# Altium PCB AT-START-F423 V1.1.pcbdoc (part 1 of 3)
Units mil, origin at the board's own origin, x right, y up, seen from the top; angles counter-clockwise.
Board outline 13392.89 x 3532.45 mil, 2 copper layers (Top Layer, Bottom Layer); 137 components, 162 nets, 618 pads, 618 vias.
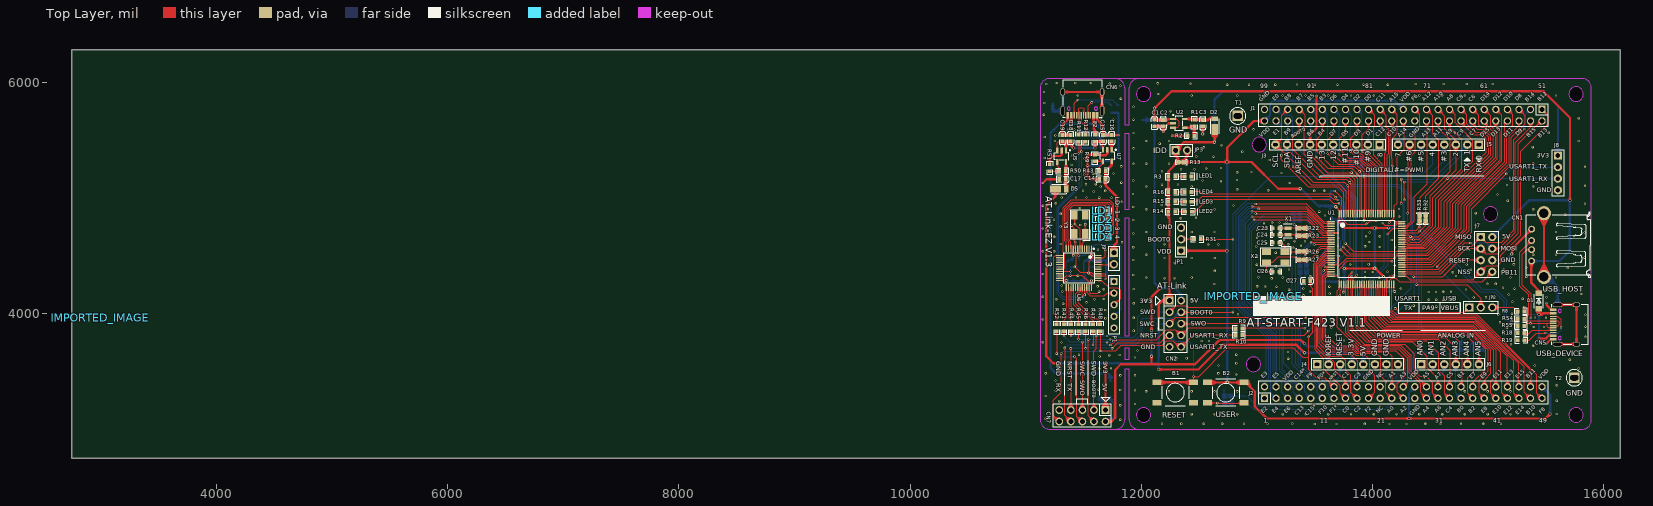
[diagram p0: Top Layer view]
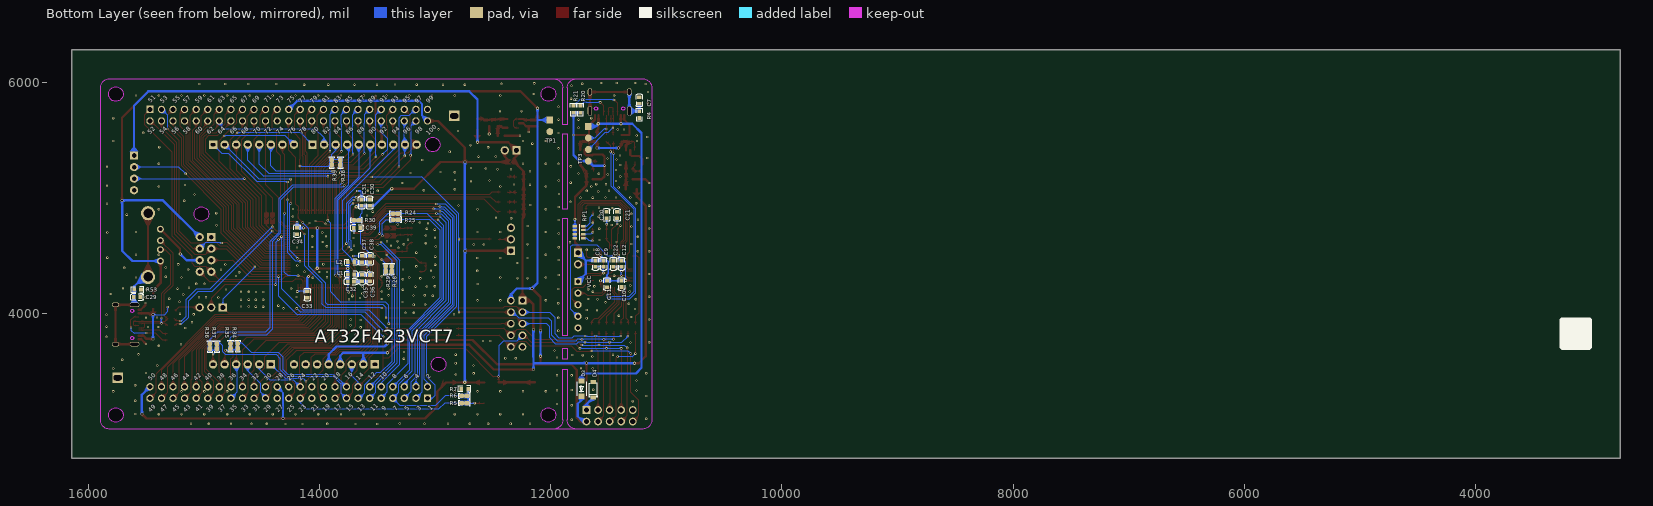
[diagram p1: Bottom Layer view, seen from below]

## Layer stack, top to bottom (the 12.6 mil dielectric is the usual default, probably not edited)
Top Layer: signal copper (thickness not stored)
Dielectric: dielectric 12.6, FR-4, Dk 4.8
Bottom Layer: signal copper (thickness not stored)

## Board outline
16142.89,2750 2750,2750 2750,6282.45 16142.89,6282.45
cut-out: 15823.04,5897.28 ccw(c15760.05,5896.97) 15697.06,5897.28 ccw(c15760.05,5897.59)
cut-out: 15823.04,3122.6 ccw(c15760.05,3122.29) 15697.06,3122.6 ccw(c15760.05,3122.91)
cut-out: 12082.89,3122.6 ccw(c12019.89,3122.6) 11956.9,3122.6 ccw(c12019.89,3122.6)
cut-out: 12082.89,5897.28 ccw(c12019.89,5897.28) 11956.9,5897.28 ccw(c12019.89,5897.28)
cut-out: 15082.49,4860.43 ccw(c15019.5,4860.02) 14956.51,4860.43 ccw(c15019.5,4860.84)
cut-out: 13032.49,3560.43 ccw(c12969.5,3560.02) 12906.51,3560.43 ccw(c12969.5,3560.84)
cut-out: 13082.49,5460.43 ccw(c13019.5,5460.02) 12956.51,5460.43 ccw(c13019.5,5460.84)

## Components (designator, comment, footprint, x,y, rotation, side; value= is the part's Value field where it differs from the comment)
B1 "BUTTON_SMT,6.0x6.0x4.5mm" BUTTON_SMT_6*6*5 12293.58,3316.11 r0 top
B2 "BUTTON_SMT,6.0x6.0x4.5mm_BUTTON_SMT_6*6*5" BUTTON_SMT_6*6*5 12730.58,3315.11 r0 top
C1 "CL10A106KP8NNNC" C0603 12113.62,5646.5 r90 top
C2 "CC0603KRX7R9BB104" C0603 12189.62,5645.5 r90 top
C3 "CL10A106KP8NNNC" C0603 12531.28,5645.68 r90 top
C7 "CC0603KRX7R9BB104" C0603 11234.18,5841.98 r270 bottom
C8 "CL10A475KO8NNNC" C0603 11613.28,4430.68 r90 bottom
C9 "CC0603KRX7R9BB104" C0603 11543.28,4430.68 r90 bottom
C10 "CC0603KRX7R9BB104" C0603 11388.28,4256.68 r90 bottom
C11 "CC0603KRX7R9BB104" C0603 11513.28,4255.68 r90 bottom
C12 "CC0603KRX7R9BB104" C0603 11388.28,4430.68 r90 bottom
C14 "CL10A106KP8NNNC" C0603 11663.28,5160.68 r0 top
C15 "CL10A106KP8NNNC" C0603 11668.28,5515.68 r270 top
C16 "CC0603KRX7R9BB104" C0603 11743.28,5515.68 r270 top
C17 "CL10A106KP8NNNC" C0603 11318.28,5160.68 r0 top
C18 "CL10A106KP8NNNC" C0603 11388.28,5515.68 r270 top
C19 "CC0603KRX7R9BB104" C0603 11318.28,5515.68 r270 top
C20 "CL10C220JB8NNNC" C0603 11516.28,4851.68 r270 bottom
C21 "CL10C220JB8NNNC" C0603 11425.28,4852.68 r270 bottom
C22 "CC0603KRX7R9BB104" C0603 11458.28,4430.68 r90 bottom
C23 "10pF" 0603_C-M 13163.28,4738.68 r180 top
C24 "10pF" 0603_C-M 13163.28,4679.68 r180 top
C25 "22pF_0603_C-M" 0603_C-M(1) 13163.88,4611.08 r180 top
C26 "22pF_0603_C-M" 0603_C-M(1) 13163.88,4361.08 r0 top
C27 "CC0603KRX7R9BB104" C0603 13431.58,4282.11 r0 top
C29 "CC0603KRX7R9BB104" C0603 15576.58,4141.11 r0 bottom
C30 "CL10A475KO8NNNC" C0603 13564.58,4958.11 r270 bottom
C31 "CC0603KRX7R9BB104" C0603 13634.58,4958.11 r270 bottom
C32 "CC0603KRX7R9BB104" C0603 13728.58,4275.11 r0 bottom
C33 "CC0603KRX7R9BB104" C0603 14104.58,4164.11 r90 bottom
C34 "CC0603KRX7R9BB104" C0603 14192.58,4713.11 r90 bottom
C35 "CL10A105KB8NNNC" C0603 13630.58,4306.11 r90 bottom
C36 "CC0603KRX7R9BB104" C0603 13561.58,4305.11 r90 bottom
C37 "CL10A105KB8NNNC" C0603 13631.58,4471.11 r270 bottom
C38 "CC0603KRX7R9BB104" C0603 13563.58,4471.11 r270 bottom
C39 "CC0603KRX7R9BB104" C0603 13674.58,4741.11 r0 bottom
CN1 "902-131A1011D10100" USB-A-TH__USB-AF-90 15427.89,4591.6 r90 top
CN2 "Z-21310110021001" HDR-TH_10P-P2.54-V-M-R2-C5-S2.54 12294.28,3911.68 r270 top
CN5 "TYPEC-304-BCP16" USB-C-SMD_TYPEC-304-BCP16#1 15662.58,3905.11 r90 top
CN6 "TYPEC-304-BCP16" USB-C-SMD_TYPEC-304-BCP16#2 11490.4,5815.68 r180 top
CN7 "Z-21310110021001" HDR-TH_10P-P2.54-V-M-R2-C5-S2.54 11490.38,3115.68 r180 top
D1 "1N5819HW-7-F" SOD-123_L2.8-W1.8-LS3.7-FD 15436.89,4106.6 r90 top
D2 "DFLS130L-7_POWERDI-123_L2.8-W1.8-LS3.7-RD" POWERDI-123_L2.8-W1.8-LS3.7-RD 12634.58,5637.11 r90 top
D3 "1N5819HW-7-F" SOD-123_L2.8-W1.8-LS3.7-FD 11733.89,3349.6 r270 bottom
D4 "SMF3.3A" SOD-123_L2.8-W1.8-LS3.7-RD 11631.88,3341.08 r90 bottom
D5 "DFLS130L-7_POWERDI-123_L2.8-W1.8-LS3.7-RD" POWERDI-123_L2.8-W1.8-LS3.7-RD 11303.28,5075.68 r0 top
F2 "SMD0603B050TF" R0603 11598.28,5515.68 r270 top
IMPORTED_IMAGE "IMPORTED_IMAGE" IMPORTED_IMAGE 3000,3964.11 r0 top
IMPORTED_IMAGE "IMPORTED_IMAGE" IMPORTED_IMAGE 12967.89,4147.6 r0 top
J1 "X6521WV-2x25H-C30D60" HDR-TH_50P-2.54-V-M-R2-C25-S2.54 14265.15,5715.15 r180 top
J2 "X6521WV-2x25H-C30D60" HDR-TH_50P-2.54-V-M-R2-C25-S2.54 14265.15,3316.57 r0 top
J3 "2.54-1*10P母" "AT-START-Connector 1x10" 13609.5,5460.43 r180 top
J4 "2.54-1*8P母环保" "AT-START-Connector 1x8" 13869.5,3560.43 r0 top
J5 "2.54-1*8P母环保" "AT-START-Connector 1x8" 14569.51,5460.43 r180 top
J6 "2.54-1*6P母" "AT-START-Connector 1x6" 14669.48,3560.43 r0 top
J7 "Header 4X2" HDR2X4 14934.51,4660.97 r270 top
J8 "Header 1x4" HDR1X4 15602.58,5366.11 r270 top
J9 "1X2P,Male,DIP_2.54" HDR1X2 11763.28,4525.68 r270 top
JP1 "Header 1x3" "HEADER 1X3" 12343.88,4542.08 r90 top
JP2 "Header 1x3" "HEADER 1X3" 14834.89,4052.61 r0 top
JP3 "NC(Header 1x2)" HDR1X2 12296.58,5411.11 r0 top
L1 "UPZ1608E601-1R0TF" L0603 13726.58,4339.11 r180 bottom
L2 "UPZ1608E601-1R0TF" L0603 13725.58,4444.11 r180 bottom
LD1 "RED" LED0603 11634.09,4889.92 r0 top
LD2 "GREEN" LED0603 11635.05,4815.83 r0 top
LD3 "BLUE" LED0603 11635.09,4738.92 r0 top
LD4 "YELLOW" LED0603 11635.05,4662.92 r0 top
LED1 "RED_LED0603(1)" LED0603 12373.58,5185.11 r0 top
LED2 "RED_LED0603" LED0603 12375.88,4879.08 r0 top
LED3 "YELLOW_LED0603" LED0603 12374.88,4965.08 r0 top
LED4 "GREEN_LED0603" LED0603 12373.88,5051.08 r0 top
P1 "HDR-M-2.54_1x5" HDR-M-2.54_1X5 11763.28,4075.68 r270 top
R1 "0603WAF5102T5E" R0603 12458.28,5647.68 r90 top
R2 "0603WAF1502T5E" R0603 12428.28,5536.68 r0 top
R3 "0603WAF1001T5E" R0603 12263.35,5184.27 r180 top
R4 "RC0603FR-071ML" R0603 11233.98,5719.99 r270 bottom
R5 "0Ω" SB-PAD 12745.89,3225.6 r180 bottom
R6 "NC_SB-PAD" SB-PAD 12745.89,3287.6 r180 bottom
R7 "0603WAF1003T5E" R0603 12743.58,3348.11 r180 bottom
R8 "0603WAF1002T5E" R0603 15282.23,4017.6 r0 top
R9 "0603WAF4700T5E" R0603 12844.55,3871.6 r0 top
R10 "0603WAF4700T5E" R0603 12844.55,3812.6 r0 top
R11 "0603WAF0000T5E" R0603 11458.28,5515.68 r270 top
R12 "0603WAF0000T5E" R0603 11518.28,5515.68 r270 top
R13 "0Ω" SB-PAD 12345.89,5308.6 r0 top
R14 "0603WAF1001T5E" R0603 12262.88,4880.08 r180 top
R15 "0603WAF1001T5E" R0603 12263.88,4967.08 r180 top
R16 "0603WAF1001T5E" R0603 12262.88,5050.08 r180 top
R18 "0603WAF5101T5E" R0603 15283.58,3831.11 r180 top
R19 "0603WAF5101T5E" R0603 15283.89,3768.6 r180 top
R20 "0603WAF5101T5E" R0603 11743.28,5765.68 r270 bottom
R21 "0603WAF5101T5E" R0603 11803.28,5765.68 r270 bottom
R22 "0Ω" SB-PAD 13386.17,4737.6 r180 top
R23 "0Ω" SB-PAD 13385.89,4672.6 r180 top
R24 "NC" SB-PAD 13340.58,4864.11 r180 bottom
R25 "NC" SB-PAD 13339.58,4810.11 r180 bottom
R26 "0Ω" SB-PAD 13384.89,4537.6 r180 top
R27 "0Ω" SB-PAD 13385.89,4464.6 r180 top
R28 "NC" SB-PAD 13373.58,4383.99 r270 bottom
R29 "NC" SB-PAD 13426.58,4386.11 r270 bottom
R30 "0Ω" SB-PAD 13678.11,4806.11 r180 bottom
R31 "0603WAF1002T5E" R0603 12484.88,4643.08 r0 top
R32 "NC_SB-PAD" SB-PAD 14458.58,4822.11 r270 top
R33 "NC_SB-PAD" SB-PAD 14405.58,4822.11 r270 top
R34 "0Ω" sb-pad 14706.89,3717.6 r270 bottom
R35 "NC_SB-PAD" sb-pad 14768.58,3718.11 r270 bottom
R36 "NC_SB-PAD" sb-pad 14946.58,3716.11 r270 bottom
R37 "0Ω" sb-pad 14885.89,3715.32 r270 bottom
R38 "NC_SB-PAD" SB-PAD 13817.88,5305.08 r270 bottom
R39 "0Ω" SB-PAD 13893.89,5305.6 r270 bottom
R41 "0603WAF330JT5E" R0603 11330.28,3876.68 r270 top
R43 "0603WAF4702T5E" R0603 11663.28,5230.68 r0 top
R44 "0603WAF330JT5E" R0603 11392.28,3876.68 r270 top
R45 "0603WAF330JT5E" R0603 11455.28,3876.68 r270 top
R46 "0603WAF330JT5E" R0603 11518.28,3876.68 r270 top
R47 "0603WAF330JT5E" R0603 11582.28,3876.68 r270 top
R48 "0603WAF330JT5E" R0603 11644.28,3876.68 r270 top
R49 "0603WAF1502T5E" R0603 11598.28,5345.68 r270 top
R50 "0603WAF5102T5E" R0603 11318.28,5230.68 r0 top
R51 "0603WAF1502T5E" R0603 11208.28,5260.68 r270 top
R52 "0603WAF330JT5E" R0603 11268.28,3876.68 r270 top
R53 "RC0603FR-071ML" R0603 15571.58,4207.11 r180 bottom
R54 "0603WAF220JT5E" R0603 15282.58,3954.11 r0 top
R55 "0603WAF220JT5E" R0603 15282.58,3892.11 r0 top
RP1 "1K" 0603*4,8P4R 11791.28,4756.68 r270 bottom
T1 "Testpoint_TESTHOOK" TESTHOOK 12833.58,5708.11 r0 top
T2 "Testpoint" TESTHOOK 15743.58,3444.11 r180 top
TP1 "2.54-1*2P母" "AT-START-TEST-POINT 1X2" 12007.58,5623.11 r270 bottom
TP3 "1X4P_2.54F" "HDR1X4 - TOP" 11674.63,5618.13 r90 bottom
U1 "AT32F423VCT7" LQFP-100_L14.0-W14.0-P0.50-LS16.0-TL 13946.58,4558.11 r0 top
U2 "RT9080N-08GJ5_SOT-23-5" SOT-23-5(1) 12339.62,5581.5 r0 top
U5 "RT9080N-08GJ5" SOT-23-5 11248.28,5345.68 r270 top
U6 "AT32F403ACxT7" LQFP-48_L7.0-W7.0-P0.50-LS9.0-BL 11460,4393.35 r180 top
U7 "RT9080N-08GJ5" SOT-23-5(1) 11643.28,5350.68 r270 top
X1 "32.768KHz" "XTAL_SOP - FC-12M" 13267.28,4738.68 r270 top
X2 "8MHz" OSC-SMD_4P-L5.0-W3.2-BL 13161.88,4488.08 r180 top
Y3 "8MHz" OSC-SMD_4P-L5.0-W3.2-BL 11468.28,4770.68 r90 top

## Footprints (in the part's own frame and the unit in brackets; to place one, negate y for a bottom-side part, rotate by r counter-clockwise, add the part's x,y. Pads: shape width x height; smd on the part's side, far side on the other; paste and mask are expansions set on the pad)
0603*4,8P4R [mm]
  rect 0.55x0.95 smd: 1(0,0) 4(2.7,0) 5(2.7,1.85) 8(0,1.85)
  rect 0.5x0.95 smd: 2(0.9,0) 3(1.8,0) 6(1.8,1.85) 7(0.9,1.85)
  silkscreen extent -0.43,0.94 3.1,0.94
0603_C-M [mil]
  rect 30x30 smd: 1(27.5,0) 2(-27.5,0)
  silkscreen extent -50,-21 50,21
0603_C-M(1) [mil]
  rect 30x30 smd: 1(27.5,0) 2(-27.5,0)
  silkscreen extent -50,-21 50,21
"AT-START-Connector 1x6" [mm]
  rect 1.86x1.86 hole 0.65 slot 1 at 0 deg: 1(-6.35,0)
  round 1.86 hole 0.65 slot 1 at 0 deg: 2(-3.81,0) 3(-1.27,0) 4(1.27,0) 5(3.81,0) 6(6.35,0)
  silkscreen extent -7.62,-1.17 7.62,1.27
"AT-START-Connector 1x8" [mm]
  rect 1.86x1.86 hole 0.65 slot 1 at 0 deg: 1(-8.89,0)
  round 1.86 hole 0.65 slot 1 at 0 deg: 2(-6.35,0) 3(-3.81,0) 4(-1.27,0) 5(1.27,0) 6(3.81,0) 7(6.35,0) 8(8.89,0)
  silkscreen extent -10.16,-1.17 10.16,1.27
"AT-START-Connector 1x10" [mm]
  rect 1.86x1.86 hole 0.65 slot 1 at 0 deg: 1(-11.43,0)
  round 1.86 hole 0.65 slot 1 at 0 deg: 2(-8.89,0) 3(-6.35,0) 4(-3.81,0) 5(-1.27,0) 6(1.27,0) 7(3.81,0) 8(6.35,0) 9(8.89,0) 10(11.43,0)
  silkscreen extent -12.7,-1.17 12.67,1.27
"AT-START-TEST-POINT 1X2" [mm]
  rect 1.5x1.5 smd: 1(-1.27,0)
  round 1.5 smd: 2(1.27,0)
BUTTON_SMT_6*6*5 [mm]
  rect 2x1.2 smd: 1(-4,2.25) 2(4,2.25) 3(-4,-2.25) 4(4,-2.25)
  silkscreen extent -3,-3 3,3
C0603 [mm]
  rect 0.8x0.9 smd: 1(-0.7,0) 2(0.7,0)
  silkscreen extent -1.41,-0.71 1.39,0.72
HDR1X2 [mm]
  rect 1.8x1.8 hole 1 slot 1.005 at 0 deg: 1(0,0)
  round 1.8 hole 1 slot 1.005 at 0 deg: 2(2.54,0)
  silkscreen extent -1.27,-1.27 3.81,1.27
HDR1X4 [mm]
  rect 1.8x1.8 hole 1: 1(0,0)
  round 1.8 hole 1: 2(2.54,0) 3(5.08,0) 4(7.62,0)
  silkscreen extent -1.27,-1.27 8.89,1.27
"HDR1X4 - TOP" [mm]
  rect 1.5x1.5 smd: 1(0,0)
  round 1.5 smd: 2(-2.54,0) 3(-5.08,0) 4(-7.62,0)
HDR2X4 [mm]
  rect 1.8x1.8 hole 1: 1(0,0)
  round 1.8 hole 1: 2(0,2.54) 3(2.54,0) 4(2.54,2.54) 5(5.08,0) 6(5.08,2.54) 7(7.62,0) 8(7.62,2.54)
  silkscreen extent -1.27,-1.27 8.89,3.81
HDR-M-2.54_1X5 [mil]
  rect 62x62 hole 35: 1(-200,0)
  round 62 hole 35: 2(-100,0) 3(0,0) 4(100,0) 5(200,0)
  silkscreen extent -250,-50 250,50
HDR-TH_10P-P2.54-V-M-R2-C5-S2.54 [mm]
  rect 1.7x1.7 hole 1.1: 1(-5.08,-1.27)
  round 1.7 hole 1.1: 2(-5.08,1.27) 3(-2.54,-1.27) 4(-2.54,1.27) 5(0,-1.27) 6(0,1.27) 7(2.54,-1.27) 8(2.54,1.27) 9(5.08,-1.27) 10(5.08,1.27)
  silkscreen extent -6.35,-2.54 6.35,2.54
HDR-TH_50P-2.54-V-M-R2-C25-S2.54 [mil]
  rect 63x63 hole 41.3: 1(-1200,-50)
  round 63 hole 41.3: 2(-1200,50) 3(-1100,-50) 4(-1100,50) 5(-1000,-50) 6(-1000,50) 7(-900,-50) 8(-900,50) 9(-800,-50) 10(-800,50) 11(-700,-50) 12(-700,50) 13(-600,-50) 14(-600,50) 15(-500,-50) 16(-500,50) 17(-400,-50) 18(-400,50) 19(-300,-50) 20(-300,50) 21(-200,-50) 22(-200,50) 23(-100,-50) 24(-100,50) 25(0,-50) 26(0,50) 27(100,-50) 28(100,50) 29(200,-50) 30(200,50) 31(300,-50) 32(300,50) 33(400,-50) 34(400,50) 35(500,-50) 36(500,50) 37(600,-50) 38(600,50) 39(700,-50) 40(700,50) 41(800,-50) 42(800,50) 43(900,-50) 44(900,50) 45(1000,-50) 46(1000,50) 47(1100,-50) 48(1100,50) 49(1200,-50) 50(1200,50)
  silkscreen extent -1250,-100 1250,100
"HEADER 1X3" [mm]
  rect 1.8x1.8 hole 1 slot 1.005 at 0 deg: 1(0,0)
  round 1.8 hole 1 slot 1.005 at 0 deg: 2(2.54,0) 3(5.08,0)
  silkscreen extent -1.27,-1.27 6.35,1.27
IMPORTED_IMAGE [mil]
L0603 [mil]
  rect 31.5x34 smd: 1(-27.6,0) 2(27.6,0)
  silkscreen extent -56,-26 56,26
LED0603 [mil]
  rect 36x32 smd: 1(-0.04,0.2) 2(60.96,0.2)
  silkscreen extent -28,-28 110,27
LQFP-48_L7.0-W7.0-P0.50-LS9.0-BL [mm]
  oval 0.27x1.5 smd: 1(-2.75,-4.25) 2(-2.25,-4.25) 3(-1.75,-4.25) 4(-1.25,-4.25) 5(-0.75,-4.25) 6(-0.25,-4.25) 7(0.25,-4.25) 8(0.75,-4.25) 9(1.25,-4.25) 10(1.75,-4.25) 11(2.25,-4.25) 12(2.75,-4.25) 25(2.75,4.25) 26(2.25,4.25) 27(1.75,4.25) 28(1.25,4.25) 29(0.75,4.25) 30(0.25,4.25) 31(-0.25,4.25) 32(-0.75,4.25) 33(-1.25,4.25) 34(-1.75,4.25) 35(-2.25,4.25) 36(-2.75,4.25)
  oval 1.5x0.27 smd: 13(4.25,-2.75) 14(4.25,-2.25) 15(4.25,-1.75) 16(4.25,-1.25) 17(4.25,-0.75) 18(4.25,-0.25) 19(4.25,0.25) 20(4.25,0.75) 21(4.25,1.25) 22(4.25,1.75) 23(4.25,2.25) 24(4.25,2.75) 37(-4.25,2.75) 38(-4.25,2.25) 39(-4.25,1.75) 40(-4.25,1.25) 41(-4.25,0.75) 42(-4.25,0.25) 43(-4.25,-0.25) 44(-4.25,-0.75) 45(-4.25,-1.25) 46(-4.25,-1.75) 47(-4.25,-2.25) 48(-4.25,-2.75)
  silkscreen extent -3.36,-4.34 3.3,3.34
LQFP-100_L14.0-W14.0-P0.50-LS16.0-TL [mil]
  oval 63x11.8 smd: 1(-305.1,236.2) 2(-305.1,216.5) 3(-305.1,196.9) 4(-305.1,177.2) 5(-305.1,157.5) 6(-305.1,137.8) 7(-305.1,118.1) 8(-305.1,98.4) 9(-305.1,78.7) 10(-305.1,59.1) 11(-305.1,39.4) 12(-305.1,19.7) 13(-305.1,0) 14(-305.1,-19.7) 15(-305.1,-39.4) 16(-305.1,-59.1) 17(-305.1,-78.7) 18(-305.1,-98.4) 19(-305.1,-118.1) 20(-305.1,-137.8) 21(-305.1,-157.5) 22(-305.1,-177.2) 23(-305.1,-196.8) 24(-305.1,-216.5) 25(-305.1,-236.2) 51(305.1,-236.2) 52(305.1,-216.5) 53(305.1,-196.8) 54(305.1,-177.2) 55(305.1,-157.5) 56(305.1,-137.8) 57(305.1,-118.1) 58(305.1,-98.4) 59(305.1,-78.7) 60(305.1,-59.1) 61(305.1,-39.4) 62(305.1,-19.7) 63(305.1,0) 64(305.1,19.7) 65(305.1,39.4) 66(305.1,59.1) 67(305.1,78.7) 68(305.1,98.4) 69(305.1,118.1) 70(305.1,137.8) 71(305.1,157.5) 72(305.1,177.2) 73(305.1,196.9) 74(305.1,216.5) 75(305.1,236.2)
  oval 11.8x63 smd: 26(-236.2,-305.1) 27(-216.5,-305.1) 28(-196.8,-305.1) 29(-177.2,-305.1) 30(-157.5,-305.1) 31(-137.8,-305.1) 32(-118.1,-305.1) 33(-98.4,-305.1) 34(-78.7,-305.1) 35(-59.1,-305.1) 36(-39.4,-305.1) 37(-19.7,-305.1) 38(0,-305.1) 39(19.7,-305.1) 40(39.4,-305.1) 41(59.1,-305.1) 42(78.7,-305.1) 43(98.4,-305.1) 44(118.1,-305.1) 45(137.8,-305.1) 46(157.5,-305.1) 47(177.2,-305.1) 48(196.9,-305.1) 49(216.5,-305.1) 50(236.2,-305.1) 76(236.2,305.1) 77(216.5,305.1) 78(196.9,305.1) 79(177.2,305.1) 80(157.5,305.1) 81(137.8,305.1) 82(118.1,305.1) 83(98.4,305.1) 84(78.7,305.1) 85(59.1,305.1) 86(39.4,305.1) 87(19.7,305.1) 88(0,305.1) 89(-19.7,305.1) 90(-39.4,305.1) 91(-59.1,305.1) 92(-78.7,305.1) 93(-98.4,305.1) 94(-118.1,305.1) 95(-137.8,305.1) 96(-157.5,305.1) 97(-177.2,305.1) 98(-196.8,305.1) 99(-216.5,305.1) 100(-236.2,305.1)
  silkscreen extent -315,-246 246,266
OSC-SMD_4P-L5.0-W3.2-BL [mm]
  rect 2x1.4 smd: 1(-2.05,-1.2) 2(2.05,-1.2) 3(2.05,1.2) 4(-2.05,1.2)
  silkscreen extent -3.46,-2.26 3.24,2.03
POWERDI-123_L2.8-W1.8-LS3.7-RD [mm]
  rect 2.4x1.5 smd: 1(-1.187,0)
  rect 1.05x1.5 smd: 2(1.187,0)
  silkscreen extent -2,-1 1.2,1
R0603 [mil]
  rect 31.75x34.02 smd: 1(-29.66,0) 2(29.66,0)
  silkscreen extent -55,-26 55,26
SB-PAD [mm]
  oval 1.225x1 smd: 1(-0.587,0)
  oval 1.319x1 smd: 2(0.541,0)
  Top Layer region: -1.2,-0.5 -1.2,0.5 -0.418,0.5 0.025,0 -0.433,-0.5
  Top Layer region: -0.119,0.5 0.381,0 -0.119,-0.5 1.2,-0.5 1.2,0.5
  silkscreen extent -1.28,-0.58 1.28,0.58
sb-pad [mm]
  oval 1.319x1 smd: 1(0.541,0)
  oval 1.225x1 smd: 2(-0.587,0)
  Top Layer region: -1.2,-0.5 -1.2,0.5 -0.418,0.5 0.025,0 -0.433,-0.5
  Top Layer region: -0.119,0.5 0.381,0 -0.119,-0.5 1.2,-0.5 1.2,0.5
  silkscreen extent -1.28,-0.58 1.28,0.58
SOD-123_L2.8-W1.8-LS3.7-FD [mil]
  rect 47.2x55.1 smd: 1(-66.9,0) 2(66.9,0)
  silkscreen extent -59,-39 59,39
SOD-123_L2.8-W1.8-LS3.7-RD [mm]
  rect 0.95x1.15 smd: 1(-1.692,0) 2(1.692,0)
  silkscreen extent -1.63,-0.94 1.41,0.94
SOT-23-5 [mil]
  rect 50x20 smd: 1(-65,100) 2(-65,63) 3(-65,25) 4(35,25) 5(35,100)
  silkscreen extent -65,1 18,135
SOT-23-5(1) [mil]
  rect 50x20 smd: 1(-65,100) 2(-65,63) 3(-65,25) 4(35,25) 5(35,100)
  silkscreen extent -65,1 18,135
TESTHOOK [mm]
  rect 2.3x2.3 hole 1.2 slot 1.8 at 0 deg: 1(0,0)
  silkscreen extent -1.79,-1.8 1.8,1.8
USB-A-TH__USB-AF-90 [mm]
  round 1.5 hole 0.9 copper offset 0,0: 1(-3.5,1.355) 4(3.5,1.355)
  round 1.5 hole 0.9: 2(-1,1.355) 3(1,1.355)
  round 3.1 hole 2.1: SH1(7,-1.355) SH2(-7,-1.355)
  silkscreen extent -7.22,-11.51 7.22,2.49
USB-C-SMD_TYPEC-304-BCP16#1 [mil]
  oval 39.4x82.7 hole 23.6 slot 70.9 at 90 deg: 13(-170.1,64.3) 14(170.1,64.3)
  oval 39.4x63 hole 23.6 slot 47.2 at 90 deg: 15(-170.1,-100.3) 16(170.1,-100.3)
  rect 23.6x57.1 smd: A1B12(-127,100.3) A4B9(-96.5,100.3) B1A12(126.8,100.3) B4A9(96.5,100.3)
  rect 11.8x57.1 smd: A5(-49.2,100.3) A6(-9.8,100.3) A7(9.8,100.3) A8(49.2,100.3) B5(68.9,100.3) B6(29.5,100.3) B7(-29.5,100.3) B8(-68.9,100.3)
  Multi-Layer board cut-out: 117.3,29.6 123.29,30.97 128.09,34.8 130.76,40.33 130.76,46.47 128.09,52.01 123.29,55.84 117.3,57.2 117.3,57.2 110.4,55.36 105.35,50.3 103.5,43.4 105.35,36.5 110.4,31.45 117.3,29.6
  Multi-Layer board cut-out: -117.3,29.6 -111.31,30.97 -106.51,34.8 -103.84,40.33 -103.84,46.47 -106.51,52.01 -111.31,55.84 -117.3,57.2 -117.3,57.2 -124.2,55.36 -129.25,50.3 -131.1,43.4 -129.25,36.5 -124.2,31.45 -117.3,29.6
  silkscreen extent -170,-200 170,120
USB-C-SMD_TYPEC-304-BCP16#2 [mil]
  oval 39.4x82.7 hole 23.6 slot 70.9 at 90 deg: 13(-170.1,64.3) 14(170.1,64.3)
  oval 39.4x63 hole 23.6 slot 47.2 at 90 deg: 15(-170.1,-100.3) 16(170.1,-100.3)
  rect 23.6x57.1 smd: A1B12(-127,100.3) A4B9(-96.5,100.3) B1A12(126.8,100.3) B4A9(96.5,100.3)
  rect 11.8x57.1 smd: A5(-49.2,100.3) A6(-9.8,100.3) A7(9.8,100.3) A8(49.2,100.3) B5(68.9,100.3) B6(29.5,100.3) B7(-29.5,100.3) B8(-68.9,100.3)
  Multi-Layer board cut-out: 103.5,43.4 105.35,36.5 110.4,31.45 117.3,29.6 124.2,31.44 129.25,36.5 131.1,43.4 131.1,43.4 129.74,49.38 125.91,54.19 120.37,56.85 114.23,56.85 108.7,54.19 104.87,49.39 103.5,43.4
  Multi-Layer board cut-out: -131.1,43.4 -129.25,36.5 -124.2,31.45 -117.3,29.6 -110.4,31.44 -105.35,36.5 -103.5,43.4 -103.5,43.4 -104.86,49.38 -108.69,54.19 -114.23,56.85 -120.37,56.85 -125.9,54.19 -129.73,49.39 -131.1,43.4
  silkscreen extent -170,-200 170,120
"XTAL_SOP - FC-12M" [mm]
  rect 0.8x1.5 smd: 1(0,0) 2(1.5,0)
  silkscreen extent -0.81,-0.99 2.29,0.94

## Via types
v1: diameter 19.68, hole 7.87, Top Layer to Bottom Layer, 317 vias
v2: diameter 19.7, hole 7.9, Top Layer to Bottom Layer, 187 vias
v3: diameter 19.7, hole 7.87, Top Layer to Bottom Layer, 72 vias
v4: diameter 27.56, hole 15.75, Top Layer to Bottom Layer, 31 vias
v5: diameter 23.62, hole 11.81, Top Layer to Bottom Layer, 11 vias

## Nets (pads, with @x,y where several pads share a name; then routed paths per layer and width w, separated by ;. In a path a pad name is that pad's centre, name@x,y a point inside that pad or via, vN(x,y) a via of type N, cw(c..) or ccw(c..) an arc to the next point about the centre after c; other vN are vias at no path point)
3V3: CN2.1 CN7.1 D2.1 D4.1 D5.1 J4.2 J4.4 J8.1 JP3.1 R3.2 R13.1 R14.2 R15.2 R16.2 | length 11400.6
  Top Layer w10: R14.2@12233.22,4880.08 12233.69,4880.55 R14.2@12234.22,4881.08 ; R15.2@12233.22,4968.08 12233.69,4967.61 R15.2@12234.22,4967.08
  Top Layer w20: D5.1@11256.53,5075.68 11256.53,5010.93 11179.28,4933.68 11179.28,3629.68 11238.88,3570.08 v4(11273.88,3570.08) ; CN7.1@11690.38,3165.68 v4@11690.38,3570.58 ; v4(12148.89,3515.6) 12491.89,3515.6 12704.89,3728.6 13341.89,3728.6 v4(13410.38,3660.11) ; v4(12149.58,3861.11) 12149.58,4078.28 12182.97,4111.68 CN2.1@12244.28,4111.68 12244.28,4822.41 12233.69,4833 12233.69,4880.55 12233.69,4967.61 R16.2@12233.69,5050.55 ; R16.2@12233.22,5050.08 R16.2@12233.69,5050.55 ; D2.1@12634.58,5590.36 12634.58,5482.28 v4(12632.89,5480.6) 12632.38,5481.11 12366.58,5481.11 JP3.1@12296.58,5411.11 12296.58,5362.11 12315.92,5342.77 12315.92,5310.11 12233.69,5227.89 R3.2@12233.69,5184.27 R16.2@12233.69,5050.55
  Bottom Layer w20: v4(11273.88,3570.08) 11689.88,3570.08 v4(11690.88,3571.08) 12149.08,3571.08 ; D4.1@11631.88,3274.45 11690.38,3215.95 CN7.1@11690.38,3165.68 ; v4(12148.89,3515.6) 12149.08,3515.78 12149.08,3571.08 ; v4(12149.58,3861.11) 12149.58,3694.11 ; v4(12632.89,5480.6) 12632.89,5849.6 12703.89,5920.6 15478.89,5920.6 15602.58,5796.91 J8.1@15602.58,5366.11 ; v4@13409.89,3660.6 v4(13410.38,3660.11) 13619.5,3660.11 ; J4.2@13619.5,3560.43 13619.5,3660.11 ; 13619.5,3661.11 13620.5,3660.11 ; J4.4@13819.5,3560.43 13819.5,3635.19 13794.58,3660.11 13620.5,3660.11 ; 12148.89,3626.17 12148.89,3693.43 12149.58,3694.11 ; 12148.89,3626.17 12149.58,3626.17 12149.58,3694.11 ; 12148.89,3626.17 12148.89,3571.26 12149.08,3571.08 ; 13619.5,3660.11 13620.5,3660.11
  other v4: 11690.88,3571.08
5V: C1.2 C2.2 CN1.1 CN2.2 CN7.2 D1.2 D3.2 J4.5 J7.2 TP1.1 U2.1 U2.3 | length 12603.5
  Top Layer w6: U2.3@12274.62,5606.5 12276.24,5608.11 12309.58,5608.11 12324.58,5623.11 12324.58,5663.11 12306.19,5681.5 U2.1@12274.62,5681.5
  Top Layer w20: CN7.2@11690.38,3065.68 11741.48,3065.68 11773.88,3098.08 11773.88,3511.58 11822.89,3560.6 12087.8,3560.6 ; v4(12087.58,3854.11) 12087.58,4142.11 v4(12161.58,4216.11) ; v4(12087.89,3630.6) 12087.89,3560.69 12087.8,3560.6 ; C1.2@12113.62,5674.06 12188.62,5674.06 C2.2@12189.62,5673.06 12225.52,5673.06 12233.58,5681.11 12274.24,5681.11 U2.1@12274.62,5681.5 ; C1.2@12113.62,5674.06 v4(12113.58,5774.11) 12260.58,5921.11 15477.58,5921.11 15705.89,5692.79 v4(15705.89,4977.6) ; v4(13409.89,3740.6) 13378.89,3771.6 12674.89,3771.6 12463.89,3560.6 12087.8,3560.6 ; CN1.1@15374.55,4453.79 15372.58,4451.82 15372.58,4263.65 15436.89,4199.34 D1.2@15436.89,4173.5
  Bottom Layer w20: CN7.2@11690.38,3065.68 11719.48,3065.68 11765.88,3112.08 11765.88,3220.08 11733.89,3252.06 D3.2@11733.89,3282.7 ; TP1.1@12007.58,5673.11 12112.38,5673.11 12113.58,5671.92 ; v4(12087.58,3854.11) 12087.58,3630.91 v4(12087.89,3630.6) ; v4(12113.58,5774.11) 12113.62,4265.07 12162.58,4216.11 12293.58,4216.11 12344.28,4165.41 CN2.2@12344.28,4111.68 ; v4(13409.89,3740.6) 13435.89,3714.6 13851.89,3714.6 13919.5,3646.99 J4.5@13919.5,3560.43 ; J7.2@15034.51,4660.97 15351.63,4978.1 15705.58,4978.1 15705.58,4543.11 15616.26,4453.79 CN1.1@15374.55,4453.79
$1N323: J9.2 U6.44 | length 137.1
  Top Layer w6: U6.44@11627.32,4422.88 11760.49,4422.89 J9.2@11763.28,4425.68
$1N349: LD4.1 RP1.5 | length 124.5
  Top Layer w6: LD4.1@11635.01,4663.13 11635.28,4663.13 11637.28,4661.13 11637.28,4630.68 v1(11639.28,4628.68)
  Bottom Layer w6: v1(11639.28,4628.68) 11665.28,4628.68 11686.98,4650.38 RP1.5@11718.45,4650.38
$1N350: LD3.1 RP1.6 | length 126.7
  Top Layer w6: LD3.1@11635.05,4739.13 11635.28,4738.9 v1(11635.28,4702.68)
  Bottom Layer w6: v1(11635.28,4702.68) 11652.15,4685.81 RP1.6@11718.45,4685.81
$1N351: LD2.1 RP1.7 | length 150.3
  Top Layer w6: LD2.1@11635.01,4816.03 11635.01,4783.95 v1(11635.28,4783.68)
  Bottom Layer w6: v1(11635.28,4783.68) 11635.28,4768.68 11682.71,4721.25 RP1.7@11718.45,4721.25
$1N352: LD1.1 RP1.8 | length 190.4
  Top Layer w6: v1(11633.28,4856.68) 11633.82,4856.14 11633.28,4856.14 v1@11634.05,4856.91 ; v1@11634.05,4855.68 LD1.1@11634.05,4890.13
  Bottom Layer w6: v1(11633.28,4856.68) 11663.28,4826.68 11663.28,4780.68 11687.28,4756.68 RP1.8@11718.45,4756.68
$1N378: C15.2 C16.2 C18.2 C19.2 F2.2 U5.1 U5.3 U7.1 U7.3 | length 872.7
  Top Layer w6: U5.3@11273.28,5410.68 11273.28,5475.68 11283.28,5485.68 11315.84,5485.68 C19.2@11318.28,5488.12 ; C15.2@11666.18,5486.02 11668.27,5483.92 U7.3@11668.27,5415.68
  Top Layer w20: U5.1@11348.28,5410.68 11348.28,5458.12 C19.2@11318.28,5488.12 C18.2@11388.28,5488.12 11388.28,5455.68 v4(11413.28,5430.68) ; v4(11598.28,5430.68) F2.2@11598.28,5486.02 11666.18,5486.02 C15.2@11668.28,5488.12 C16.2@11743.28,5488.12 U7.1@11743.27,5415.68
  Bottom Layer w20: v4(11413.28,5430.68) v4(11598.28,5430.68)
$1N419: R50.1 R51.2 U5.4 | length 166.8
  Top Layer w10: R51.2@11208.28,5231.02 11288.28,5231.02 R50.1@11288.62,5230.68 11288.62,5260.34 11273.28,5275.68 U5.4@11273.28,5310.68
$1N495: R43.1 R49.2 U7.4 | length 173.4
  Top Layer w10: R49.2@11598.28,5306.02 11607.94,5315.68 U7.4@11668.27,5315.68 11668.27,5295.67 11633.62,5261.02 R43.1@11633.62,5230.68
$2N102: C25.2 R26.2 X2.1 | length 227.8
  Top Layer w6: C25.2@13191.38,4611.08 13213.61,4611.08 13242.59,4582.1 X2.1@13242.59,4535.32 13356.46,4535.32 R26.2@13359.22,4538.08
$2N103: C26.2 R27.2 X2.3 | length 431.5
  Top Layer w6: C26.2@13136.38,4361.08 13098.61,4361.08 13081.17,4378.52 X2.3@13081.17,4440.84 13131.3,4440.84 13177.58,4487.11 13336.18,4487.11 R27.2@13359.22,4464.08
$2N208: C24.2 R23.2 X1.2 | length 173.7
  Top Layer w6: C24.2@13190.78,4679.68 X1.2@13267.22,4679.68 ; X1.2@13267.28,4679.62 13268.77,4681.11 13321.58,4681.11 13330.61,4672.08 R23.2@13360.22,4672.08
$2N210: C23.2 R22.2 X1.1 | length 168.7
  Top Layer w6: C23.2@13190.78,4738.68 X1.1@13267.28,4738.68 13358.62,4738.68 R22.2@13359.22,4738.08
$2N318: JP1.2 R31.1 | length 111.7
  Top Layer w6: JP1.2@12343.89,4642.08 12454.22,4642.08 R31.1@12455.22,4643.08
$3N116: C3.2 D2.2 R1.2 U2.5 | length 268.7
  Top Layer w20: U2.5@12374.62,5681.5 12454.12,5681.5 R1.2@12458.28,5677.34 12527.18,5677.34 C3.2@12531.28,5673.24 12572.45,5673.24 12573.58,5672.11 12585.33,5683.86 D2.2@12634.58,5683.86
$3N117: R1.1 R2.2 U2.4 | length 170.2
  Top Layer w20: U2.4@12374.62,5606.5 12416.19,5606.5 12416.58,5606.11 12428.48,5618.02 R1.1@12458.28,5618.02 12458.28,5537.02 R2.2@12457.94,5536.68
$3N122: LED1.1 R3.1 | length 81
  Top Layer w10: R3.1@12293.01,5184.27 12372.48,5184.27 LED1.1@12373.53,5185.32
$3N126: B2.3 B2.4 R5.2 R6.2 R7.2 | length 494.3
  Top Layer w6: B2.3@12573.09,3226.52 12574.5,3225.11 v3(12657.58,3225.11) 12886.65,3225.11 B2.4@12888.06,3226.52
  Bottom Layer w6: v3(12657.58,3225.11) 12711.92,3225.11 12713.92,3227.11 R7.2@12713.92,3348.11
$3N170: LED3.1 R15.1 | length 82
  Top Layer w10: R15.1@12293.54,4967.08 12295.33,4965.28 LED3.1@12374.83,4965.28
$3N171: LED2.1 R14.1 | length 83.6
  Top Layer w10: R14.1@12292.54,4880.08 12375.04,4880.08 LED2.1@12375.83,4879.28
$3N172: LED4.1 R16.1 | length 81.8
  Top Layer w10: R16.1@12292.54,5050.08 12372.63,5050.08 LED4.1@12373.83,5051.28
$3N7076: CN5.A5 R18.1 | length 262.2
  Top Layer w6: R18.1@15313.24,3824.11 15349.41,3824.11 15381.21,3855.91 CN5.A5@15562.27,3855.91
$3N7077: CN5.B5 R19.1 | length 519.1
  Top Layer w6: R19.1@15313.55,3768.6 15354.89,3768.6 15416.89,3830.6 v2(15496.89,3830.6) ; CN5.B5@15562.27,3974.01 15600.48,3974.01 15628.89,3945.6 v2(15628.89,3878.6)
  Bottom Layer w6: v2(15496.89,3830.6) 15602.81,3830.6 15628.89,3856.68 v2(15628.89,3878.6)
$3N33030: JP2.3 R8.1 | length 232.2
  Top Layer w6: JP2.3@15034.9,4052.6 15217.57,4052.6 R8.1@15252.57,4017.6
$4N197: J6.5 R34.1 R35.1 | length 239.4
  Top Layer w6: v3(14810.58,3682.11) 14819.48,3673.2 J6.5@14819.48,3560.43
  Bottom Layer w6: R34.1@14706.58,3687.45 14759.19,3687.45 R35.1@14768.58,3696.83 14783.3,3682.11 v3(14810.58,3682.11)
$4N198: J6.6 R36.1 R37.1 | length 203.7
  Top Layer w6: J6.6@14919.48,3560.43 14919.88,3560.82 v3(14919.88,3648.61)
  Bottom Layer w6: v3(14919.88,3648.61) 14885.58,3682.91 14885.58,3684.45 14936.19,3684.45 R36.1@14946.58,3694.83
$4N262: J3.3 R38.1 R39.1 | length 220.6
  Bottom Layer w6: R38.1@13817.88,5328.2 13823.42,5333.74 13894.88,5333.74 13894.88,5375.81 13859.5,5411.19 J3.3@13859.5,5460.43
ATLINK_5V: CN6.A4B9 CN6.B4A9 D3.1 F2.1 TP3.1 | length 3389
  Top Layer w20: CN6.B4A9@11393.9,5715.38 v4@11393.9,5640.68 ; CN6.A4B9@11586.9,5715.38 11586.9,5639.3 v4(11588.28,5640.68) 11588.28,5595.68 11598.28,5585.68 F2.1@11598.28,5545.34 ; v4@11393.9,5640.68 11393.28,5635.68 11393.9,5635.05 v4@11393.9,5640.68
  Bottom Layer w20: TP3.1@11674.63,5618.13 11610.83,5618.13 v4(11588.28,5640.68) v4(11393.28,5640.68) 11295.28,5640.68 11214.28,5559.68 11214.28,3530.2 11263.4,3481.08 11713.41,3481.08 11733.89,3460.6 D3.1@11733.89,3416.5
ATLK_RX: CN2.10 CN7.10 R10.1 R48.2 | length 2431.9
  Top Layer w6: CN7.10@11290.38,3065.68 11236.88,3119.18 11236.88,3248.08 11307.88,3319.08 v1(11307.88,3655.08) ; R48.2@11644.28,3847.02 11644.28,3700.48 11644.68,3700.08 11644.68,3680.28 v1@11644.48,3680.08 ; R10.1@12814.89,3812.6 12445.2,3812.6 CN2.10@12344.28,3711.68 12327.01,3711.68 12276.61,3762.08 12216.54,3762.08 12175.58,3721.11 11820.91,3721.11 11774.88,3675.08 v1@11644.48,3675.08 ; v1@11644.48,3675.08 11643.88,3679.48 v1@11644.48,3680.08 ; v1@11644.48,3675.08 v1@11644.48,3680.08
  Bottom Layer w6: v1(11307.88,3655.08) 11327.88,3675.08 v1(11643.88,3675.08)
ATLK_TX: CN2.8 CN7.8 R9.1 R47.2 | length 2381.7
  Top Layer w6: v1(11337.88,3703.08) 11337.88,3465.08 11336.88,3464.08 11336.88,3119.18 CN7.8@11390.38,3065.68 ; R47.2@11582.28,3847.02 v1@11582.28,3727.08 ; v1(11731.88,3727.08) 11736.54,3727.08 11784.19,3774.73 12130.19,3774.73 12216.54,3861.08 12294.88,3861.08 CN2.8@12344.28,3811.68 12404.2,3871.6 ; 12401.2,3871.6 12404.2,3871.6 ; R9.1@12814.89,3871.6 12404.2,3871.6 ; v1@11582.28,3727.08 11582.88,3722.28 11582.28,3721.68 v1@11582.28,3727.08
  Bottom Layer w6: v1(11337.88,3703.08) 11361.88,3727.08 v1(11582.88,3727.08) v1(11731.88,3727.08)
BOOT0: CN2.4 CN7.4 J1.44 R31.2 R45.2 U1.94 | length 5524.5
  Top Layer w6: R45.2@11455.28,3847.02 v1@11455.28,3777.08 ; v1(11540.88,3776.08) 11540.88,3115.18 CN7.4@11590.38,3065.68 ; CN2.4@12344.28,4011.68 12792.81,4011.68 v2(12792.89,4011.6) ; R31.2@12514.54,4643.08 v2(12792.89,4643.1) ; J1.44@13365.15,5665.15 13365.15,5575.62 13309.58,5520.04 13309.58,5419.11 v3(13547.58,5181.11) 13550.58,5178.11 13792.58,5178.11 13828.48,5142.21 U1.94@13828.48,4863.21 ; v1@11455.28,3777.08 11455.88,3773.08 11455.28,3772.48 v1@11455.28,3777.08
  Bottom Layer w6: v1(11455.88,3777.08) 11456.88,3776.08 v1(11540.88,3776.08) v1(11730.88,3776.08) 11769.96,3776.08 11784.93,3761.11 11938.58,3761.11 11988.58,3811.11 11988.58,3931.11 12018.54,3961.08 12271.54,3961.08 12322.14,4011.68 CN2.4@12344.28,4011.68 ; v2(12792.89,4011.6) v2(12792.89,4643.1) 12792.89,4860.6 13113.41,5181.11 v3(13547.58,5181.11)
CC1: CN6.A5 R20.1 | length 312.5
  Top Layer w6: CN6.A5@11539.6,5715.38 11539.6,5797 v1(11571.36,5826.01) 11571.68,5826.33 v1@11568.93,5826.33
  Bottom Layer w6: v1(11571.36,5826.01) 11690.56,5826.01 11690.89,5825.68 11712.94,5825.68 R20.1@11743.28,5795.34
CC2: CN6.B5 R21.1 | length 521.3
  Top Layer w6: CN6.B5@11421.5,5715.38 11421.5,5818.9 v1@11450.2,5847.6 ; v1@11450.2,5847.6 11451.59,5847.6 11450.38,5847.78 v1@11450.2,5847.6
  Bottom Layer w6: v1(11451.08,5847.09) 11451.86,5847.87 11750.75,5847.87 R21.1@11803.28,5795.34
EGND: C29.2 CN1.SH1 CN1.SH2 CN5.13 CN5.14 CN5.15 CN5.16 R53.1 | length 1534.8
  Top Layer w20: CN1.SH2@15481.24,4316 CN1.SH1@15481.24,4867.18 ; CN5.13@15598.27,3735.01 CN5.15@15762.88,3735.01 CN5.16@15762.88,4075.21 CN5.14@15598.27,4075.21
  Bottom Layer w20: CN1.SH2@15481.24,4316 15520.02,4316.01 15600.92,4235.11 15600.92,4159.01 15600.01,4158.11 15600.01,4076.95 CN5.14@15598.27,4075.21
EGND2: C7.2 CN6.13 CN6.14 CN6.15 CN6.16 R4.1 | length 824.7
  Top Layer w20: CN6.16@11320.3,5915.98 CN6.15@11660.5,5915.98 CN6.13@11660.5,5751.38
  Bottom Layer w20: R4.1@11233.98,5745.65 R4.1@11234.18,5745.85 ; C7.2@11234.18,5812.42 R4.1@11234.18,5745.85 ; CN6.16@11320.3,5915.98 CN6.14@11320.3,5751.38 11239.7,5751.38 R4.1@11234.18,5745.85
